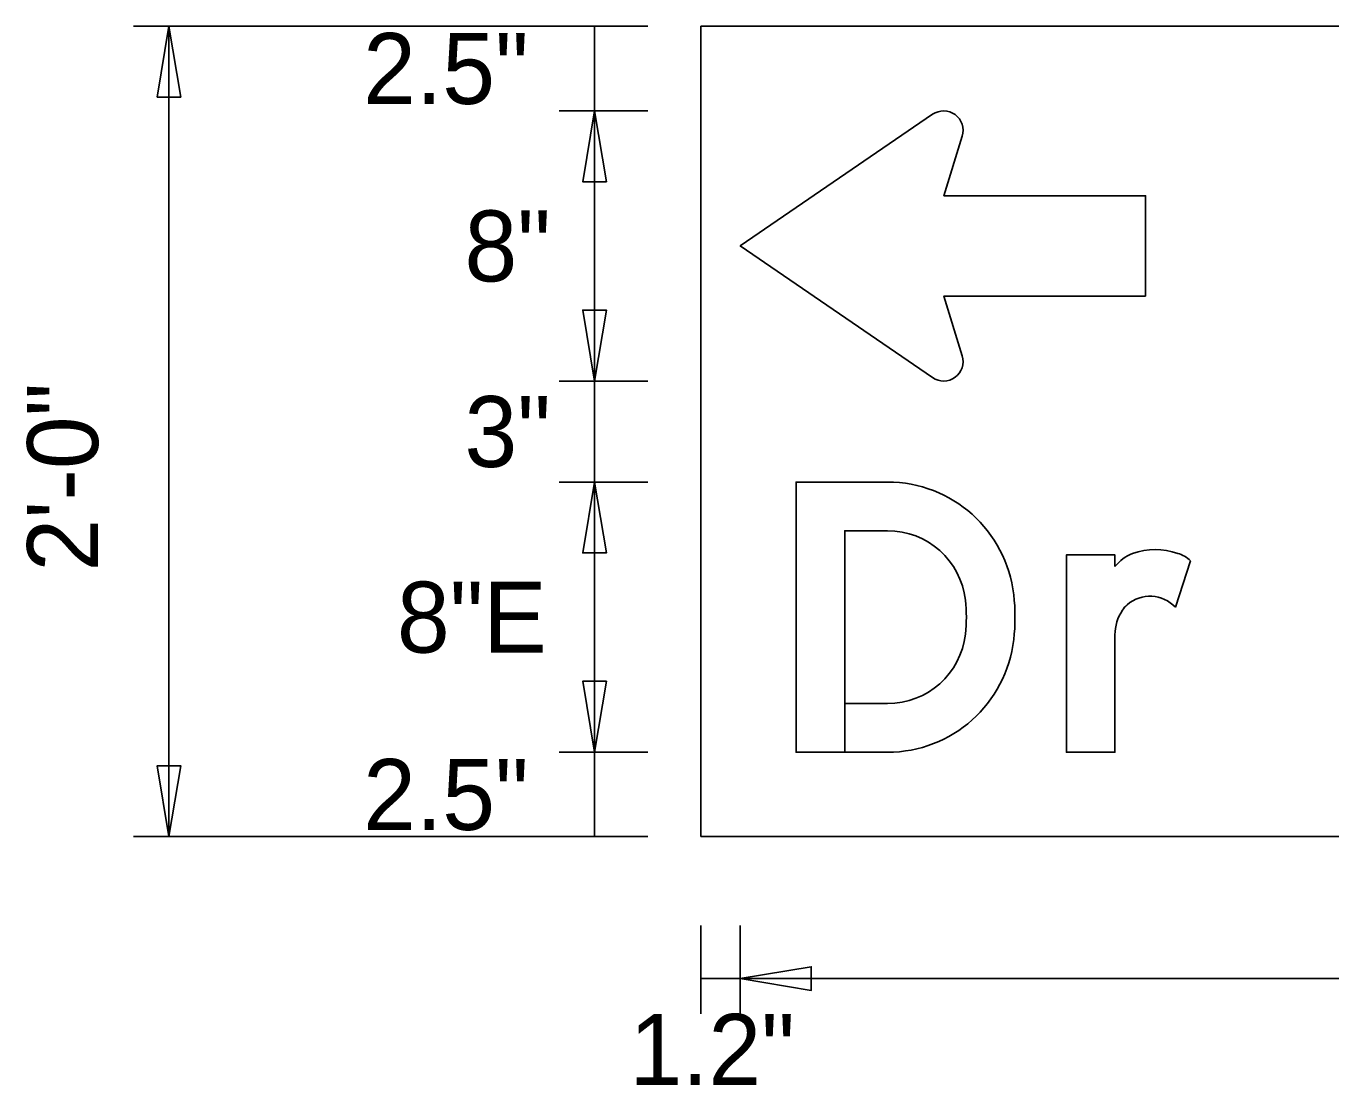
# Model space of a CAD drawing. Extents: x 1374 to 1480, y 568 to 638.
# Drawn here: x 1413.193 to 1416.413, y 629.461 to 632.074 of the extents above; entities that cross this region are included whole.
import ezdxf

# ---------------------------------------------------------------- set-up
doc = ezdxf.new("R2010")
doc.units = 0
for name, color, linetype in [('GSBWFill', 7, 'Continuous'), ('GSColorFill', 7, 'Continuous'), ('GSDims', 7, 'Continuous'), ('GSOutline', 7, 'Continuous')]:
    doc.layers.add(name, color=color, linetype=linetype)

msp = doc.modelspace()

# ---------------------------------------------------------------- linework, layer by layer
at = {"layer": 'GSBWFill'}
for p, q in [((1423.8581, 632.074), (1414.8581, 632.074)), ((1414.8581, 632.074), (1414.8581, 630.074)), ((1416.0291, 630.6399), (1416.0665, 630.7546)), ((1416.0665, 630.7546), (1416.0665, 630.7546)), ((1415.2132, 630.2823), (1415.3187, 630.2823)), ((1414.8581, 630.074), (1423.8581, 630.074))]:
    msp.add_line(p, q, dxfattribs=at)
for points in [[(1415.4299, 631.8564), (1414.9553, 631.5315), (1415.4299, 631.2066)], [(1415.9553, 631.4078), (1415.9553, 631.6552), (1415.4578, 631.6552), (1415.503, 631.8026)], [(1415.503, 631.2604), (1415.4578, 631.4078), (1415.9553, 631.4078)], [(1415.3187, 630.949), (1415.0932, 630.949), (1415.0932, 630.2823), (1415.2132, 630.2823), (1415.2132, 630.829), (1415.3187, 630.829)], [(1415.8799, 630.7403), (1415.8799, 630.769), (1415.7599, 630.769), (1415.7599, 630.2823), (1415.8799, 630.2823), (1415.8799, 630.5719)], [(1415.3187, 630.4023), (1415.2132, 630.4023), (1415.2132, 630.2823)]]:
    msp.add_lwpolyline(points, dxfattribs=at)
for centre, start, end in [((1415.457, 631.8167), 342.9427, 124.3997), ((1415.457, 631.2463), 235.6003, 17.0573)]:
    msp.add_arc(centre, 0.0481, start, end, dxfattribs=at)
for centre, major_axis, ratio, start_param, end_param in [((1415.3187, 630.6356), (0, 0.3133), 0.999994, 4.82584, 6.283185), ((1415.3187, 630.6356), (0, 0.1933), 0.999994, 4.82584, 6.283185), ((1415.968, 630.6687), (0, 0.1135), 0.999989, 0.405268, 0.888298), ((1415.979, 630.6089), (0, 0.1734), 0.999989, 5.955439, 6.610932), ((1416.0122, 630.6978), (0, 0.0786), 0.999989, 5.519323, 5.990814), ((1415.9664, 630.5813), (0, 0.0859), 0.999989, 5.464387, 6.998975), ((1415.1432, 630.6156), (0, 0.37), 0.999994, 4.598938, 4.82584), ((1415.1432, 630.6156), (0, 0.49), 0.999994, 4.598938, 4.82584), ((1415.9537, 630.5958), (0, 0.0667), 0.999989, 0.71579, 0.982393), ((1415.9895, 630.5719), (0, 0.1096), 0.999989, 0.982393, 1.570796), ((1415.3187, 630.5956), (0, 0.1933), 0.999994, 3.141593, 4.598938), ((1415.3187, 630.5956), (0, 0.3133), 0.999994, 3.141593, 4.598938)]:
    msp.add_ellipse(centre, major_axis=major_axis, ratio=ratio, start_param=start_param, end_param=end_param, dxfattribs=at)
at = {"layer": 'GSColorFill'}
for p, q in [((1423.8581, 632.074), (1414.8581, 632.074)), ((1414.8581, 632.074), (1414.8581, 630.074)), ((1423.8581, 632.074), (1414.8581, 632.074)), ((1414.8581, 632.074), (1414.8581, 630.074)), ((1416.0291, 630.6399), (1416.0665, 630.7546)), ((1416.0665, 630.7546), (1416.0665, 630.7546)), ((1415.2132, 630.2823), (1415.3187, 630.2823)), ((1414.8581, 630.074), (1423.8581, 630.074)), ((1414.8581, 630.074), (1423.8581, 630.074))]:
    msp.add_line(p, q, dxfattribs=at)
for points in [[(1415.4299, 631.8564), (1414.9553, 631.5315), (1415.4299, 631.2066)], [(1415.9553, 631.4078), (1415.9553, 631.6552), (1415.4578, 631.6552), (1415.503, 631.8026)], [(1415.503, 631.2604), (1415.4578, 631.4078), (1415.9553, 631.4078)], [(1415.3187, 630.949), (1415.0932, 630.949), (1415.0932, 630.2823), (1415.2132, 630.2823), (1415.2132, 630.829), (1415.3187, 630.829)], [(1415.8799, 630.7403), (1415.8799, 630.769), (1415.7599, 630.769), (1415.7599, 630.2823), (1415.8799, 630.2823), (1415.8799, 630.5719)], [(1415.3187, 630.4023), (1415.2132, 630.4023), (1415.2132, 630.2823)]]:
    msp.add_lwpolyline(points, dxfattribs=at)
for centre, start, end in [((1415.457, 631.8167), 342.9427, 124.3997), ((1415.457, 631.2463), 235.6003, 17.0573)]:
    msp.add_arc(centre, 0.0481, start, end, dxfattribs=at)
for centre, major_axis, ratio, start_param, end_param in [((1415.3187, 630.6356), (0, 0.3133), 0.999994, 4.82584, 6.283185), ((1415.3187, 630.6356), (0, 0.1933), 0.999994, 4.82584, 6.283185), ((1415.968, 630.6687), (0, 0.1135), 0.999989, 0.405268, 0.888298), ((1415.979, 630.6089), (0, 0.1734), 0.999989, 5.955439, 6.610932), ((1416.0122, 630.6978), (0, 0.0786), 0.999989, 5.519323, 5.990814), ((1415.9664, 630.5813), (0, 0.0859), 0.999989, 5.464387, 6.998975), ((1415.1432, 630.6156), (0, 0.37), 0.999994, 4.598938, 4.82584), ((1415.1432, 630.6156), (0, 0.49), 0.999994, 4.598938, 4.82584), ((1415.9537, 630.5958), (0, 0.0667), 0.999989, 0.71579, 0.982393), ((1415.9895, 630.5719), (0, 0.1096), 0.999989, 0.982393, 1.570796), ((1415.3187, 630.5956), (0, 0.1933), 0.999994, 3.141593, 4.598938), ((1415.3187, 630.5956), (0, 0.3133), 0.999994, 3.141593, 4.598938)]:
    msp.add_ellipse(centre, major_axis=major_axis, ratio=ratio, start_param=start_param, end_param=end_param, dxfattribs=at)
at = {"layer": 'GSDims'}
for p, q in [((1413.6769, 632.074), (1413.4581, 632.074)), ((1413.5456, 630.074), (1413.5456, 632.074)), ((1414.7269, 632.074), (1413.6769, 632.074)), ((1414.7269, 632.074), (1414.5081, 632.074)), ((1414.5956, 631.8648), (1414.5956, 632.074)), ((1414.7269, 631.8648), (1414.5081, 631.8648)), ((1414.7269, 631.8648), (1414.5081, 631.8648)), ((1414.5956, 631.8648), (1414.5956, 631.1981)), ((1414.7269, 631.1981), (1414.5081, 631.1981)), ((1414.7269, 631.1981), (1414.5081, 631.1981)), ((1414.5956, 630.949), (1414.5956, 631.1981)), ((1414.7269, 630.949), (1414.5081, 630.949)), ((1414.7269, 630.949), (1414.5081, 630.949)), ((1414.5956, 630.949), (1414.5956, 630.2823)), ((1414.7269, 630.2823), (1414.5081, 630.2823)), ((1414.7269, 630.2823), (1414.5081, 630.2823)), ((1414.5956, 630.074), (1414.5956, 630.2823)), ((1413.6769, 630.074), (1413.4581, 630.074)), ((1414.7269, 630.074), (1413.6769, 630.074)), ((1414.7269, 630.074), (1414.5081, 630.074)), ((1414.8581, 629.8552), (1414.8581, 629.6365)), ((1414.8581, 629.8552), (1414.8581, 629.6365)), ((1414.9553, 629.8552), (1414.9553, 629.6365)), ((1414.9553, 629.8552), (1414.9553, 629.6365)), ((1414.8581, 629.724), (1414.9553, 629.724)), ((1414.9553, 629.724), (1423.7623, 629.724))]:
    msp.add_line(p, q, dxfattribs=at)
for points in [[(1413.5456, 632.074), (1413.5748, 631.899), (1413.5165, 631.899)], [(1414.5956, 631.8648), (1414.6248, 631.6898), (1414.5665, 631.6898)], [(1414.5956, 631.1981), (1414.6248, 631.3731), (1414.5665, 631.3731)], [(1414.5956, 630.949), (1414.6248, 630.774), (1414.5665, 630.774)], [(1414.5956, 630.2823), (1414.6248, 630.4573), (1414.5665, 630.4573)], [(1413.5456, 630.074), (1413.5748, 630.249), (1413.5165, 630.249)], [(1414.9553, 629.724), (1415.1303, 629.7531), (1415.1303, 629.6948)]]:
    msp.add_lwpolyline(points, close=True, dxfattribs=at)
at = {"layer": 'GSOutline'}
for p, q in [((1423.8581, 632.074), (1414.8581, 632.074)), ((1414.8581, 632.074), (1414.8581, 630.074)), ((1416.0291, 630.6399), (1416.0665, 630.7546)), ((1416.0665, 630.7546), (1416.0665, 630.7546)), ((1415.2132, 630.4023), (1415.3187, 630.4023)), ((1414.8581, 630.074), (1423.8581, 630.074))]:
    msp.add_line(p, q, dxfattribs=at)
for points in [[(1415.4299, 631.8564), (1414.9553, 631.5315), (1415.4299, 631.2066)], [(1415.9553, 631.4078), (1415.9553, 631.6552), (1415.4578, 631.6552), (1415.503, 631.8026)], [(1415.503, 631.2604), (1415.4578, 631.4078), (1415.9553, 631.4078)], [(1415.3187, 630.949), (1415.0932, 630.949), (1415.0932, 630.2823), (1415.3187, 630.2823)], [(1415.3187, 630.829), (1415.2132, 630.829), (1415.2132, 630.4023)], [(1415.8799, 630.7403), (1415.8799, 630.769), (1415.7599, 630.769), (1415.7599, 630.2823), (1415.8799, 630.2823), (1415.8799, 630.5719)]]:
    msp.add_lwpolyline(points, dxfattribs=at)
for centre, start, end in [((1415.457, 631.8167), 342.9427, 124.3997), ((1415.457, 631.2463), 235.6003, 17.0573)]:
    msp.add_arc(centre, 0.0481, start, end, dxfattribs=at)
for centre, major_axis, ratio, start_param, end_param in [((1415.3187, 630.6356), (0, 0.3133), 0.999994, 4.82584, 6.283185), ((1415.3187, 630.6356), (0, 0.1933), 0.999994, 4.82584, 6.283185), ((1415.968, 630.6687), (0, 0.1135), 0.999989, 0.405268, 0.888298), ((1415.979, 630.6089), (0, 0.1734), 0.999989, 5.955439, 6.610932), ((1416.0122, 630.6978), (0, 0.0786), 0.999989, 5.519323, 5.990814), ((1415.9664, 630.5813), (0, 0.0859), 0.999989, 5.464387, 6.998975), ((1415.1432, 630.6156), (0, 0.37), 0.999994, 4.598938, 4.82584), ((1415.1432, 630.6156), (0, 0.49), 0.999994, 4.598938, 4.82584), ((1415.9537, 630.5958), (0, 0.0667), 0.999989, 0.71579, 0.982393), ((1415.9895, 630.5719), (0, 0.1096), 0.999989, 0.982393, 1.570796), ((1415.3187, 630.5956), (0, 0.1933), 0.999994, 3.141593, 4.598938), ((1415.3187, 630.5956), (0, 0.3133), 0.999994, 3.141593, 4.598938)]:
    msp.add_ellipse(centre, major_axis=major_axis, ratio=ratio, start_param=start_param, end_param=end_param, dxfattribs=at)

# ---------------------------------------------------------------- texts
at = {"layer": 'GSDims'}
for s, p in [('2.5"', (1414.0248, 631.8819)), ('8"', (1414.2748, 631.444)), ('3"', (1414.2748, 630.9861)), ('8"E', (1414.1081, 630.5281)), ('2.5"', (1414.0248, 630.0906)), ('1.2"', (1414.6817, 629.4615))]:
    msp.add_text(s, height=0.175, dxfattribs=at).set_placement(p)
msp.add_text('2\'-0"', height=0.175, rotation=90, dxfattribs=at).set_placement((1413.3706, 630.7281))

doc.saveas('drawing.dxf')
